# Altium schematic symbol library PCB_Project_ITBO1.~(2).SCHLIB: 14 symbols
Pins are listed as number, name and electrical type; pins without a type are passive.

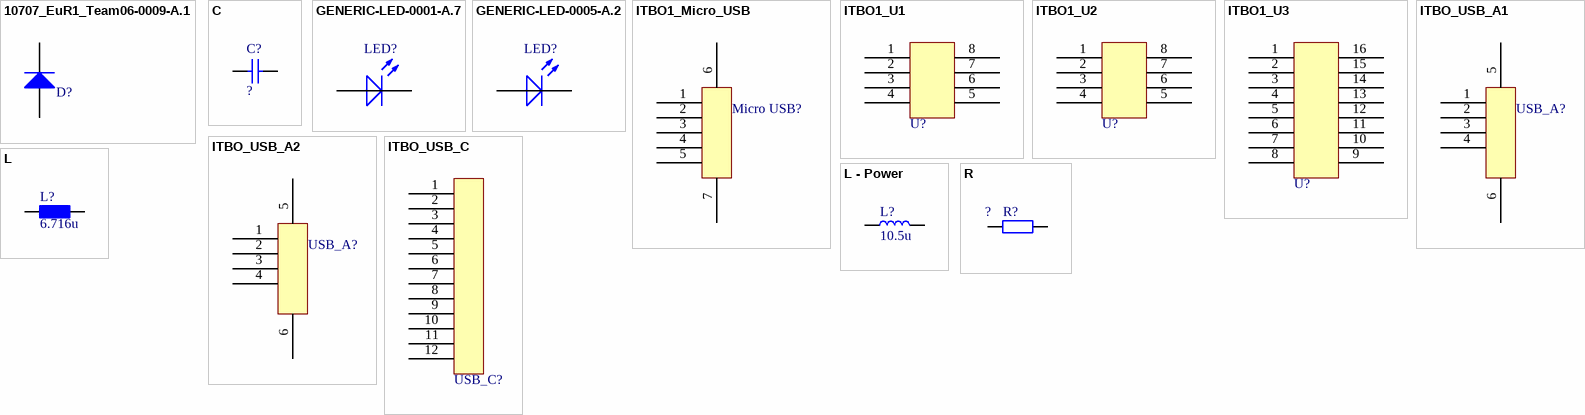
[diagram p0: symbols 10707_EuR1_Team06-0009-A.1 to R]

## 10707_EuR1_Team06-0009-A.1
designator D?, comment 1N4148W-7-F  (value not drawn)
Fast Switching Diode, 100 V, 2 A, 300 mA; Manufacturer: Diodes Incorporated
footprint DIODES_SOD123_2_H
pins: 1 K, 2 A

## C
designator C?, comment ?
Capacitor; #Manufacturer: Generic Components; #Publisher: Dr. A. Heinzelmann; #Class: Passive; Initial Voltage: 0V
footprint 0805
simulation model CAP (Capacitor)
footprint 1210
footprint 0603
footprint CC-Type-B-3528 (Chip Capacitor; Body 3.5 x 2.8 mm (LxW typ))
footprint 1206 (SMD Chip 1206)
footprint 0402 (SMD Chip 0402)
footprint 1812 (Chip Capacitor; Body 4.5 x 3.2 mm (LxW typ))
footprint 0402 - R (SMD Chip 0402 - Reflow)
footprint 0603 - R (SMD Chip 0603 - Reflow)
footprint 0805 - R (SMD Chip 0805 - Reflow)
footprint 1206 - R (SMD Chip 1206 - Reflow)
pins: 1, 2

## GENERIC-LED-0001-A.7
designator LED?, comment tbd  (value not drawn)
LED red; Manufacturer: generic; #ClassSub: LEDs; #Class: Generic-Components
footprint LED-RED-0603[1608]  - RFL (SMD Chip 0603 - LED RED - RFL)
footprint LED-RED-0603[1608] (SMD Chip 0603 - LED RED)
footprint LED-RED-0805[2012] (SMD Chip 0805 - LED RED)
footprint LED-RED-0805[2012]  - RFL (SMD Chip 0805 - LED RED - RFL)
pins: 1 K, 2 A

## GENERIC-LED-0005-A.2
designator LED?, comment tbd  (value not drawn)
LED blue; Manufacturer: generic; #ClassSub: LEDs; #Class: Generic-Components
footprint LED-BLUE-0603[1608]  - RFL (SMD Chip 0603 - LED BLUE - RFL)
footprint LED-BLUE-0805[2012]  - RFL (SMD Chip 0805 - LED BLUE - RFL)
footprint LED-BLUE-0805[2012] (SMD Chip 0805 - LED BLUE)
footprint LED-BLUE-0603[1608] (SMD Chip 0603 - LED BLUE)
pins: 1 K, 2 A

## ITBO1_Micro_USB
designator Micro USB?  (value not drawn)
footprint MOLEX_1051330001
pins: 1, 2, 3, 4, 5, 6, 7

## ITBO1_U1
designator U?  (value not drawn)
footprint ITBO1_U1 (TSOP, 8-Leads, Body 4.85x3.85mm, Pitch 1.27mm, IPC Medium Density)
pins: 1, 2, 3, 4, 5, 6, 7, 8

## ITBO1_U2
designator U?  (value not drawn)
footprint ITBO1_U2 (TSOP, 8-Leads, Body 4.85x3.85mm, Pitch 1.27mm, IPC Medium Density)
pins: 1, 2, 3, 4, 5, 6, 7, 8

## ITBO1_U3
designator U?  (value not drawn)
footprint ITBO1_U3
pins: 1, 2, 3, 4, 5, 6, 7, 8, 9, 10, 11, 12, 13, 14, 15, 16

## ITBO_USB_A1
designator USB_A?  (value not drawn)
footprint MOLEX_48037-0001
pins: 1, 2, 3, 4, 5, 6

## ITBO_USB_A2
designator USB_A?  (value not drawn)
footprint MOLEX_48037-0001
pins: 1, 2, 3, 4, 5, 6

## ITBO_USB_C
designator USB_C?  (value not drawn)
footprint MOLEX_105450-0101
pins: 1, 2, 3, 4, 5, 6, 7, 8, 9, 10, 11, 12

## L
designator L?  value 6.716u  (hidden comment: L)
Inductor; #Manufacturer: Generic Components; #Publisher: Dr. A. Heinzelmann; #Class: Passive; #ClassSub: Resistor
simulation model Inductor (ideal Inductor)
footprint 0805 (SMD Chip 0805)
footprint 1206 (SMD Chip 1206)
footprint 0603 (SMD Chip 0603)
footprint 0402 (SMD Chip 0402)
footprint 1210 (SMD Chip 1210)
footprint 0402 - R (SMD Chip 0402 - Reflow)
footprint 0805 - R (SMD Chip 0805 - Reflow)
footprint 0603 - R (SMD Chip 0603 - Reflow)
footprint SRR1240 (Footprint not found)
footprint 1806 - R (Body 5 x 2 mm (LxW typ))
footprint WE-PD (Power Choke WE-PD)
pins: 1, 2

## L - Power
designator L?, comment 10.5u
Inductor - Power; #Manufacturer: Generic Components; #Publisher: Dr. A. Heinzelmann; #Class: Passive; #ClassSub: Resistor
simulation model Inductor (ideal Inductor)
footprint WE-TPC (Power-Choke WE-TPC 2.8 x 2.8)
pins: 1, 2

## R
designator R?, comment ?
Resistor; #Manufacturer: Generic Components; #Publisher: Dr. A. Heinzelmann; #Class: Passive
simulation model RESISTOR (Resistor (Standard))
footprint 0805 (SMD Chip 0805)
footprint 1206 (SMD Chip 1206)
footprint 0603 (SMD Chip 0603)
footprint 0402 (SMD Chip 0402)
footprint 0402 - R (SMD Chip 0402 - Reflow)
footprint 1206 - R (SMD Chip 1206 - Reflow)
footprint 0603 - R (SMD Chip 0603 - Reflow)
footprint 0805 - R (SMD Chip 0805 - Reflow)
footprint 2512[6332] (SMD Chip 250 x 120 mil or 6.3 x 3.2 mm)
footprint 2010[5025] (SMD Chip 200 x 100 mil or 5.0 x 2.5 mm)
footprint 02016 (SMD Chip 02016)
footprint AXIAL-0.4 (Resistor; 2 Leads)
pins: 1, 2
